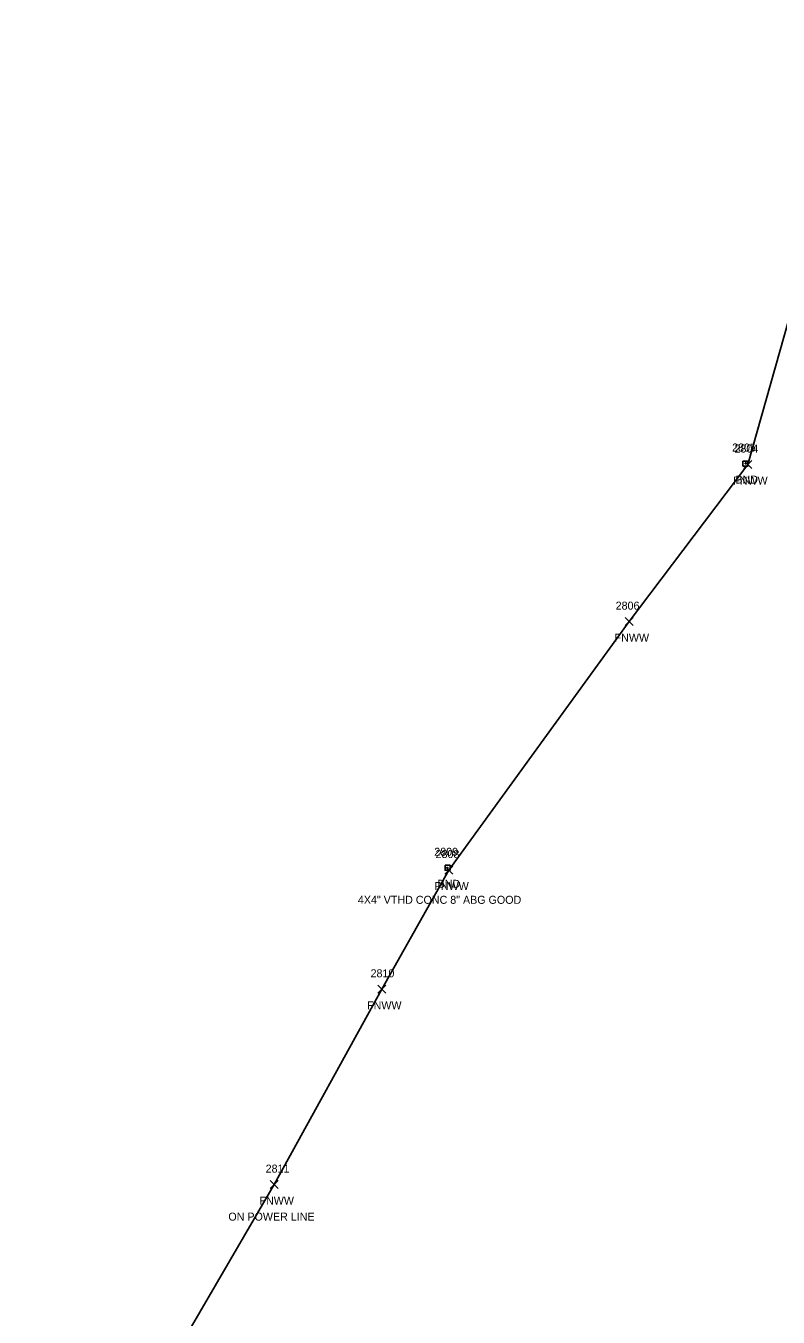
# Model space of a CAD drawing. Extents: x 1472022 to 1479249, y 777216 to 786527.
# Drawn here: x 1473097.6 to 1473285.6, y 778752 to 779074.7 of the extents above; entities that cross this region are included whole.
import ezdxf

# ---------------------------------------------------------------- set-up
doc = ezdxf.new("R2010")
doc.units = 0
for name, color, linetype in [('L_A', 7, 'Continuous'), ('L_C', 7, 'Continuous'), ('L_I', 7, 'Continuous'), ('L_TIC', 7, 'Continuous'), ('Level 18', 7, 'Continuous'), ('LFNC', 7, 'Continuous'), ('M_A', 7, 'Continuous'), ('M_C', 7, 'Continuous'), ('M_I', 7, 'Continuous')]:
    doc.layers.add(name, color=color, linetype=linetype)

msp = doc.modelspace()

# ---------------------------------------------------------------- linework, layer by layer
at = {"layer": 'L_TIC'}
for points in [[(1473277.06, 778964.07), (1473279.06, 778966.07)], [(1473279.06, 778964.07), (1473277.06, 778966.07)], [(1473247.41, 778924.8), (1473249.41, 778926.8)], [(1473249.41, 778924.8), (1473247.41, 778926.8)], [(1473202.34, 778862.73), (1473204.34, 778864.73)], [(1473204.34, 778862.73), (1473202.34, 778864.73)], [(1473185.54, 778832.93), (1473187.54, 778834.93)], [(1473187.54, 778832.93), (1473185.54, 778834.93)], [(1473158.66, 778784.12), (1473160.66, 778786.12)], [(1473160.66, 778784.12), (1473158.66, 778786.12)]]:
    msp.add_lwpolyline(points, dxfattribs=at)
at = {"layer": 'Level 18'}
for points in [[(1473276.83, 778965.94), (1473278.08, 778965.94), (1473278.08, 778964.69), (1473276.83, 778964.69)], [(1473202.4, 778864.92), (1473203.65, 778864.92), (1473203.65, 778863.67), (1473202.4, 778863.67)]]:
    msp.add_lwpolyline(points, close=True, dxfattribs=at)
for centre in [(1473277.46, 778965.32), (1473203.03, 778864.29)]:
    msp.add_circle(centre, 0.0833, dxfattribs=at)
at = {"layer": 'LFNC'}
msp.add_lwpolyline([(1473307.53, 779075.77), (1473302.37, 779055.02), (1473291.71, 779013.38), (1473278.06, 778965.07), (1473248.41, 778925.8), (1473203.34, 778863.73), (1473186.54, 778833.93), (1473159.66, 778785.12), (1473137.27, 778746.63), (1473131.18, 778719.11), (1473124.89, 778691.16), (1473117.49, 778666.71), (1473112.14, 778636.96), (1473112.13, 778637.02), (1473099.55, 778583.54), (1473097.59, 778571.13), (1473104.16, 778540.32), (1473121.35, 778447.02)], dxfattribs=at)

# ---------------------------------------------------------------- texts
at = {"layer": 'L_A'}
for p in [(1473274.4, 778960.07), (1473244.76, 778920.8), (1473199.69, 778858.73), (1473182.89, 778828.93), (1473156, 778780.12)]:
    msp.add_text('FNWW', height=2, dxfattribs=at).set_placement(p)
at = {"layer": 'L_C'}
msp.add_text('ON POWER LINE', height=2, dxfattribs=at).set_placement((1473148.22, 778776.12))
at = {"layer": 'L_I'}
for s, p in [('2804', (1473274.72, 778968.07)), ('2806', (1473245.02, 778928.8)), ('2808', (1473200.01, 778866.73)), ('2810', (1473183.76, 778836.93)), ('2811', (1473157.53, 778788.12))]:
    msp.add_text(s, height=2, dxfattribs=at).set_placement(p)
at = {"layer": 'M_A'}
for p in [(1473274.94, 778960.32), (1473200.51, 778859.29)]:
    msp.add_text('BND', height=2, dxfattribs=at).set_placement(p)
at = {"layer": 'M_C'}
msp.add_text('4X4" VTHD CONC 8" ABG GOOD', height=2, dxfattribs=at).set_placement((1473180.59, 778855.29))
at = {"layer": 'M_I'}
for s, p in [('2805', (1473274.12, 778968.32)), ('2809', (1473199.68, 778867.29))]:
    msp.add_text(s, height=2, dxfattribs=at).set_placement(p)

doc.saveas('drawing.dxf')
